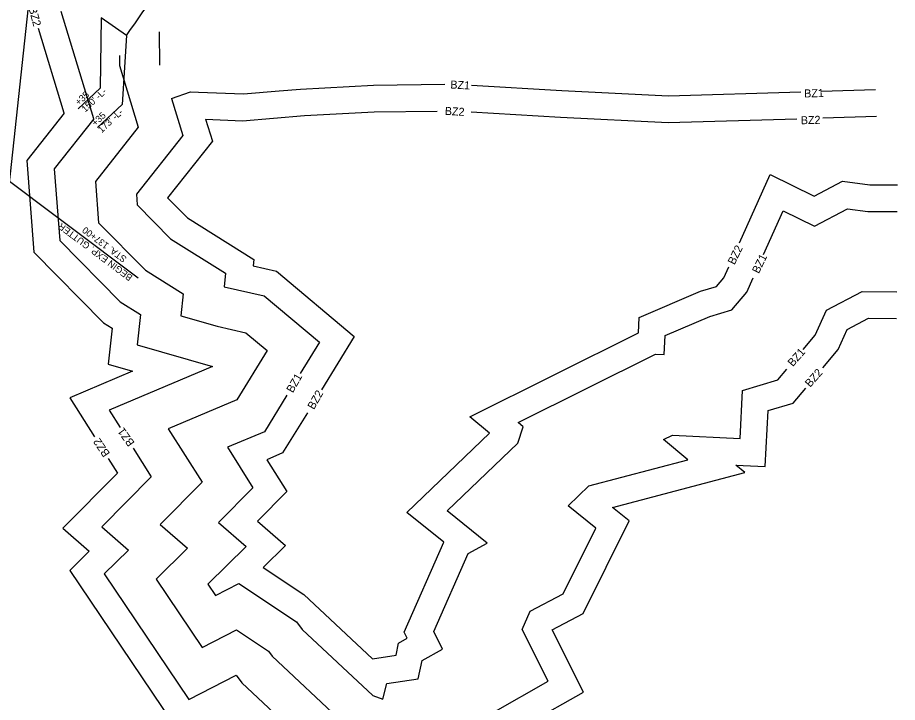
# Model space of a CAD drawing. Extents: x 2384780 to 2405432, y 547869 to 573706.
# Drawn here: x 2399633 to 2400292, y 560642 to 561155 of the extents above; entities that cross this region are included whole.
import ezdxf

# ---------------------------------------------------------------- set-up
doc = ezdxf.new("R2010")
doc.units = 0
for name, color, linetype in [('Old_Level_41', 7, 'Continuous'), ('Old_Level_5', 7, 'Continuous'), ('Old_Level_6', 7, 'Continuous'), ('Old_Level_63', 7, 'Continuous'), ('Prop Buffer Zone 1', 7, 'Continuous'), ('Prop Buffer Zone 2', 7, 'Continuous')]:
    doc.layers.add(name, color=color, linetype=linetype)

msp = doc.modelspace()

# ---------------------------------------------------------------- linework, layer by layer
at = {"layer": 'Old_Level_41'}
msp.add_line((2399641.94, 561174.31), (2399625.41, 561021.59), dxfattribs=at)
at = {"layer": 'Old_Level_5'}
msp.add_line((2399544.89, 561093.47), (2399723.29, 560960.09), dxfattribs=at)
at = {"layer": 'Old_Level_6'}
for p, q in [((2399738.86, 561144.31), (2399739.17, 561119.28)), ((2399709.08, 561126.36), (2399709.18, 561118.91)), ((2399709.18, 561118.91), (2399723.26, 561072.83)), ((2399723.26, 561072.83), (2399691.08, 561032.08)), ((2399691.08, 561032.08), (2399693.43, 561001.29)), ((2399693.43, 561001.29), (2399728.56, 560965.67)), ((2399728.56, 560965.67), (2399756.79, 560948.01)), ((2399756.79, 560948.01), (2399755.01, 560931.64)), ((2399755.01, 560931.64), (2399782.26, 560923.75)), ((2399782.26, 560923.75), (2399803.92, 560918.83)), ((2399803.92, 560918.83), (2399819.84, 560905.51)), ((2399819.84, 560905.51), (2399797.2, 560868.67)), ((2399797.2, 560868.67), (2399745.75, 560847.01)), ((2399745.75, 560847.01), (2399771.03, 560806.86)), ((2399771.03, 560806.86), (2399739.66, 560775.15)), ((2399739.66, 560775.15), (2399760.02, 560757.43)), ((2399760.02, 560757.43), (2399736.6, 560734.4)), ((2399736.6, 560734.4), (2399771.2, 560683.21)), ((2399771.2, 560683.21), (2399796.74, 560696.35)), ((2399796.74, 560696.35), (2399820.72, 560680.42)), ((2399820.72, 560680.42), (2399823.45, 560676.67)), ((2399823.45, 560676.67), (2399883.04, 560621))]:
    msp.add_line(p, q, dxfattribs=at)
at = {"layer": 'Old_Level_63'}
msp.add_line((2399714.37, 561141.44), (2399695.57, 561154.68), dxfattribs=at)
for points in [[(2399695.57, 561154.68), (2399694.82, 561102.1), (2399678.18, 561086.59)], [(2399714.37, 561141.44), (2399711.08, 561089.76), (2399692.62, 561072.54)]]:
    msp.add_lwpolyline(points, dxfattribs=at)
msp.add_arc((2395689.31, 563976), 4923, 324.84572, 325.84689, dxfattribs=at)
at = {"layer": 'Prop Buffer Zone 1'}
for p, q in [((2399689.98, 561079.09), (2399665.4, 561159.48)), ((2399748.06, 561094.32), (2399756.55, 561066.56)), ((2399689.98, 561079.09), (2399660.27, 561041.48)), ((2399756.55, 561066.56), (2399721.88, 561022.68)), ((2399660.27, 561041.48), (2399664.36, 560988.04)), ((2399721.88, 561022.68), (2399722.51, 561014.53)), ((2399722.51, 561014.53), (2399747.45, 560989.23)), ((2400191.73, 560977.34), (2400206.5, 561010.21)), ((2400206.5, 561010.21), (2400229.77, 560998.74)), ((2400229.77, 560998.74), (2400254.59, 561011.66)), ((2400254.59, 561011.66), (2400269.91, 561009.68)), ((2400269.91, 561009.68), (2400291.87, 561009.53)), ((2399664.36, 560988.04), (2399709.67, 560942.1)), ((2399747.45, 560989.23), (2399788.65, 560963.47)), ((2399788.65, 560963.47), (2399787.54, 560953.31)), ((2400179.07, 560949.19), (2400183.93, 560960)), ((2399787.54, 560953.31), (2399817.62, 560946.48)), ((2400168.04, 560935.95), (2400179.07, 560949.19)), ((2400238.84, 560935.81), (2400265.51, 560949.7)), ((2400265.51, 560949.7), (2400291.47, 560949.53)), ((2399709.67, 560942.1), (2399724.93, 560932.55)), ((2399817.62, 560946.48), (2399858.96, 560911.89)), ((2400151.36, 560931.04), (2400168.04, 560935.95)), ((2400230.43, 560917.09), (2400238.84, 560935.81)), ((2399724.93, 560932.55), (2399722.46, 560909.83)), ((2400117.94, 560916.73), (2400151.36, 560931.04)), ((2400117.21, 560902.54), (2400117.94, 560916.73)), ((2400221.45, 560906.32), (2400230.43, 560917.09)), ((2399722.46, 560909.83), (2399778.86, 560893.5)), ((2399858.96, 560911.89), (2399844.46, 560888.28)), ((2400007.9, 560851.63), (2400110.75, 560902.87)), ((2400110.75, 560902.87), (2400117.21, 560902.54)), ((2399778.86, 560893.5), (2399701.52, 560860.94)), ((2400202.46, 560883.54), (2400209.23, 560891.65)), ((2400175.92, 560875.72), (2400202.46, 560883.54)), ((2400174.08, 560839.57), (2400175.92, 560875.72)), ((2399834.48, 560872.04), (2399817.72, 560844.76)), ((2399701.52, 560860.94), (2399709.74, 560847.88)), ((2400011.71, 560848.45), (2400007.9, 560851.63)), ((2399817.72, 560844.76), (2399789.98, 560833.08)), ((2400007.67, 560836.27), (2400011.71, 560848.45)), ((2400116.81, 560838.85), (2400123.42, 560842.15)), ((2400123.42, 560842.15), (2400174.08, 560839.57)), ((2399954.73, 560785.6), (2400007.67, 560836.27)), ((2400135.01, 560823.65), (2400116.81, 560838.85)), ((2399719.48, 560832.43), (2399732.95, 560811.03)), ((2399789.98, 560833.08), (2399809.11, 560802.7)), ((2400060.89, 560804.15), (2400135.01, 560823.65)), ((2399732.95, 560811.03), (2399695.84, 560773.52)), ((2399809.11, 560802.7), (2399783.47, 560776.78)), ((2400045.35, 560789.28), (2400060.89, 560804.15)), ((2400065.98, 560772.52), (2400045.35, 560789.28)), ((2399984.74, 560761.22), (2399954.73, 560785.6)), ((2399783.47, 560776.78), (2399804.16, 560758.76)), ((2399695.84, 560773.52), (2399715.87, 560756.09)), ((2400041.47, 560723.24), (2400065.98, 560772.52)), ((2399804.16, 560758.76), (2399775.43, 560730.51)), ((2399970.33, 560753.65), (2399984.74, 560761.22)), ((2399715.87, 560756.09), (2399697.76, 560738.29)), ((2399944.59, 560695.09), (2399970.33, 560753.65)), ((2399697.76, 560738.29), (2399761.25, 560644.35)), ((2399775.43, 560730.51), (2399781.15, 560722.06)), ((2399781.15, 560722.06), (2399798.67, 560731.08)), ((2399798.67, 560731.08), (2399841.81, 560702.42)), ((2400016.81, 560710.29), (2400041.47, 560723.24)), ((2400010.87, 560696.76), (2400016.81, 560710.29)), ((2399841.81, 560702.42), (2399846.03, 560696.63)), ((2399846.03, 560696.63), (2399898.88, 560647.26)), ((2399951.14, 560682.03), (2399944.59, 560695.09)), ((2400030.35, 560657.87), (2400010.87, 560696.76)), ((2399935.96, 560673.45), (2399951.14, 560682.03)), ((2399933.07, 560659.74), (2399935.96, 560673.45)), ((2399761.25, 560644.35), (2399796.62, 560662.55)), ((2399796.62, 560662.55), (2399800.87, 560656.7)), ((2399909.36, 560656.13), (2399933.07, 560659.74)), ((2399989.08, 560634.55), (2400030.35, 560657.87)), ((2399800.87, 560656.7), (2399867.21, 560594.74)), ((2399906.6, 560644.59), (2399909.36, 560656.13)), ((2399898.88, 560647.26), (2399906.6, 560644.59))]:
    msp.add_line(p, q, dxfattribs=at)
for points in [[(2399748.06, 561094.32), (2399762.33, 561099.36), (2399768.37, 561099.1)], [(2399768.37, 561099.1), (2399802.02, 561097.66), (2399828.76, 561099.97), (2399844.82, 561101.37), (2399899.42, 561104.37), (2399953.01, 561104.9)], [(2399973.01, 561104.35), (2400040.56, 561100.25), (2400120.38, 561096.37), (2400219.64, 561099.23)], [(2400234.95, 561099.74), (2400275.56, 561101.1)]]:
    msp.add_lwpolyline(points, dxfattribs=at)
at = {"layer": 'Prop Buffer Zone 2'}
for p, q in [((2399667.79, 561083.26), (2399648.43, 561146.59)), ((2399667.79, 561083.26), (2399639.73, 561047.74)), ((2399773.7, 561078.86), (2399778.74, 561062.39)), ((2399778.74, 561062.39), (2399745.23, 561019.97)), ((2399639.73, 561047.74), (2399644.98, 560979.21)), ((2400173.82, 560986.29), (2400196.76, 561037.32)), ((2400196.76, 561037.32), (2400229.53, 561021.16)), ((2400229.53, 561021.16), (2400250.92, 561032.31)), ((2400250.92, 561032.31), (2400271.27, 561029.67)), ((2400271.27, 561029.67), (2400292, 561029.53)), ((2399745.23, 561019.97), (2399760.05, 561004.95)), ((2399760.05, 561004.95), (2399809.89, 560973.78)), ((2399644.98, 560979.21), (2399697.08, 560926.38)), ((2399809.89, 560973.78), (2399809.35, 560968.87)), ((2399809.35, 560968.87), (2399826.75, 560964.92)), ((2400161.96, 560959.89), (2400165.69, 560968.2)), ((2399826.75, 560964.92), (2399885.05, 560916.14)), ((2400156.56, 560953.42), (2400161.96, 560959.89)), ((2400098.6, 560930.21), (2400144.58, 560949.89)), ((2400144.58, 560949.89), (2400156.56, 560953.42)), ((2400098.02, 560918.87), (2400098.6, 560930.21)), ((2400254.24, 560921.28), (2400270.35, 560929.67)), ((2400270.35, 560929.67), (2400291.33, 560929.53)), ((2399697.08, 560926.38), (2399703.69, 560922.25)), ((2399703.69, 560922.25), (2399700.76, 560895.3)), ((2400247.55, 560906.39), (2400254.24, 560921.28)), ((2399885.05, 560916.14), (2399860.49, 560876.16)), ((2399971.6, 560855.89), (2400098.02, 560918.87)), ((2400236.1, 560892.66), (2400247.55, 560906.39)), ((2399700.76, 560895.3), (2399719.03, 560890.01)), ((2399719.03, 560890.01), (2399672.04, 560870.22)), ((2400213.94, 560866.06), (2400223.38, 560877.39)), ((2399672.04, 560870.22), (2399690.54, 560840.84)), ((2400195.17, 560860.54), (2400213.94, 560866.06)), ((2399849.95, 560859.01), (2399831.4, 560828.82)), ((2399986.36, 560843.56), (2399971.6, 560855.89)), ((2400193.03, 560818.58), (2400195.17, 560860.54)), ((2399924.52, 560784.38), (2399986.36, 560843.56)), ((2399831.4, 560828.82), (2399819.46, 560823.79)), ((2399700.64, 560824.8), (2399707.57, 560813.81)), ((2399819.46, 560823.79), (2399834.5, 560799.92)), ((2400170.94, 560819.7), (2400193.03, 560818.58)), ((2400177.57, 560814.17), (2400170.94, 560819.7)), ((2399707.57, 560813.81), (2399666.63, 560772.44)), ((2400078.52, 560788.11), (2400177.57, 560814.17)), ((2399834.5, 560799.92), (2399812.68, 560777.87)), ((2399952.13, 560761.94), (2399924.52, 560784.38)), ((2400091.02, 560777.95), (2400078.52, 560788.11)), ((2399812.68, 560777.87), (2399833.6, 560759.66)), ((2400056.5, 560708.54), (2400091.02, 560777.95)), ((2399666.63, 560772.44), (2399686.43, 560755.2)), ((2399833.6, 560759.66), (2399816.74, 560743.08)), ((2399922.5, 560694.54), (2399952.13, 560761.94)), ((2399686.43, 560755.2), (2399671.87, 560740.88)), ((2399816.74, 560743.08), (2399847.36, 560722.75)), ((2399671.87, 560740.88), (2399754.62, 560618.45)), ((2399847.36, 560722.75), (2399898.75, 560674.75)), ((2400033.41, 560696.42), (2400056.5, 560708.54)), ((2399924.73, 560690.08), (2399922.5, 560694.54)), ((2400056.75, 560649.82), (2400033.41, 560696.42)), ((2399916.35, 560677.42), (2399918.25, 560686.42)), ((2399918.25, 560686.42), (2399924.73, 560690.08)), ((2399898.75, 560674.75), (2399916.35, 560677.42)), ((2400006.79, 560621.59), (2400056.75, 560649.82))]:
    msp.add_line(p, q, dxfattribs=at)
for points in [[(2399773.7, 561078.86), (2399801.32, 561077.67), (2399847.72, 561081.5), (2399900.07, 561084.38), (2399947.26, 561084.84)], [(2399972.67, 561084.33), (2400039.47, 561080.28), (2400120.19, 561076.36), (2400216.71, 561079.14)], [(2400236.2, 561079.77), (2400276.23, 561081.11)]]:
    msp.add_lwpolyline(points, dxfattribs=at)

# ---------------------------------------------------------------- texts
at = {"layer": 'Old_Level_5'}
for s, p in [('BEGIN EXP. GUTTER', (2399719.39, 560961.21)), ('STA. 137+00', (2399715.06, 560975.07))]:
    msp.add_text(s, height=5, rotation=143.19711, dxfattribs=at).set_placement(p)
at = {"layer": 'Old_Level_63'}
for s, p in [('+35', (2399678.72, 561088.78)), ("150' -L-", (2399683.49, 561083.66)), ('+35', (2399691.1, 561073.27)), ("173' -L-", (2399695.87, 561068.16))]:
    msp.add_text(s, height=5, rotation=43.00003, dxfattribs=at).set_placement(p)
at = {"layer": 'Prop Buffer Zone 1'}
for rotation, p in [(64.25303, (2400188.17, 560962.71)), (48.58035, (2400213.66, 560893.05)), (60.16916, (2399839, 560873.4)), (125.78751, (2399720.81, 560836.49))]:
    msp.add_text('BZ1', height=6, rotation=rotation, dxfattribs=at).set_placement(p)
at = {"layer": 'Prop Buffer Zone 2'}
for s, rotation, p in [('BZ2', 285.10053, (2399640.96, 561161.96)), ('BZ1', 356.68364, (2399956.95, 561101.82)), ('BZ1', 1.51148, (2400222.24, 561095.01)), ('BZ2', 356.67034, (2399952.79, 561082.07)), ('BZ2', 1.49818, (2400219.75, 561074.98)), ('BZ2', 64.23973, (2400169.96, 560969.31)), ('BZ2', 48.56705, (2400226.63, 560877.59)), ('BZ2', 60.15586, (2399854.81, 560860.86)), ('BZ2', 123.97232, (2399702.31, 560828.43))]:
    msp.add_text(s, height=6, rotation=rotation, dxfattribs=at).set_placement(p)

doc.saveas('drawing.dxf')
